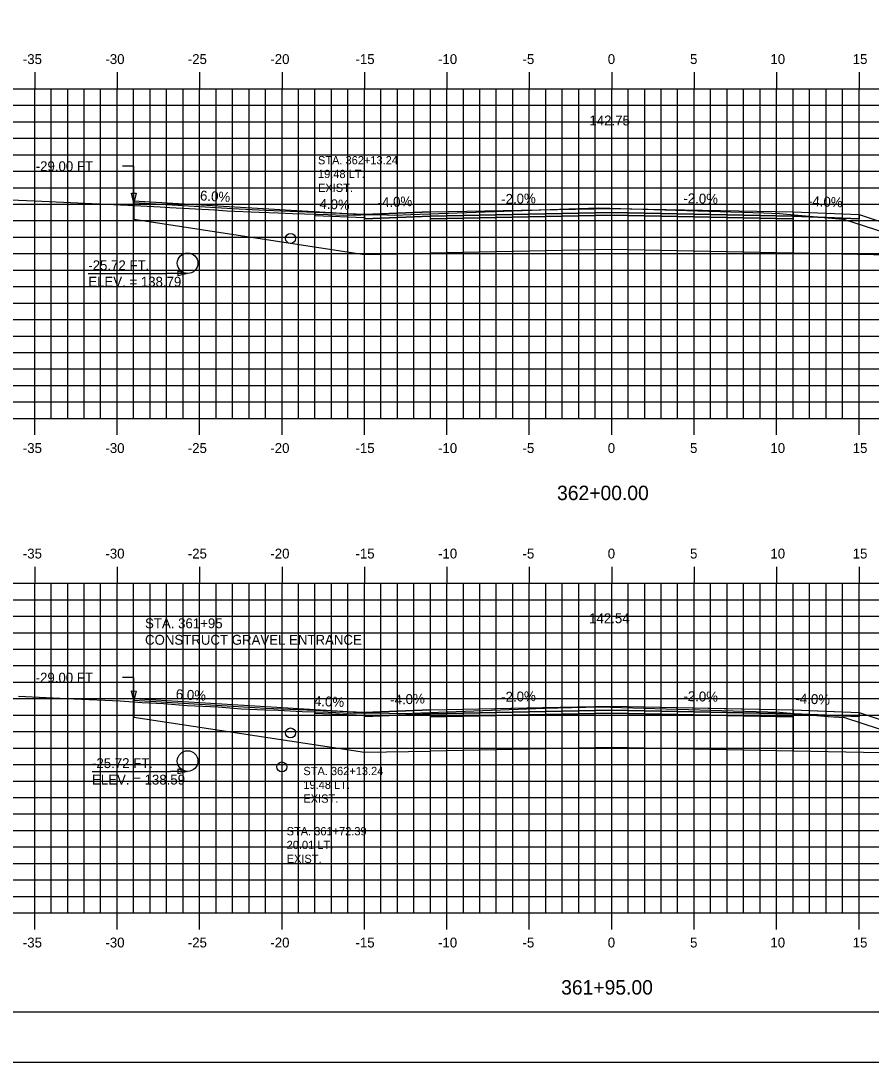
# Model space of a CAD drawing. Extents: x 1146746 to 1146916, y 608981 to 609091.
# Drawn here: x 1146793.6 to 1146845.2, y 608981.3 to 609044.5 of the extents above; entities that cross this region are included whole.
import ezdxf

# ---------------------------------------------------------------- set-up
doc = ezdxf.new("R2010")
doc.units = 0
for name, color, linetype in [('ANNOTATION', 7, 'Continuous'), ('BORDER', 7, 'Continuous'), ('D_Drainage_Culvert', 7, 'Continuous'), ('D_Roadway_Centerline', 7, 'Continuous'), ('D_Roadway_Centerline_Text', 7, 'Continuous'), ('D_Roadway_Edge_Shoulder', 7, 'Continuous'), ('D_Roadway_Edge_TW', 7, 'Continuous'), ('D_Roadway_Pavement', 7, 'Continuous'), ('D_Roadway_SubGrade', 7, 'Continuous'), ('D_Text_Monospaced', 7, 'Continuous'), ('D_Text_Standard', 7, 'Continuous'), ('H_V ANNOTATION', 7, 'Continuous'), ('MAJOR', 7, 'Continuous'), ('MINOR', 7, 'Continuous'), ('PLOT BOUNDARY', 7, 'Continuous'), ('S_Drainage_Invert', 7, 'Continuous'), ('S_Roadway_Centerline', 7, 'Continuous')]:
    doc.layers.add(name, color=color, linetype=linetype)

msp = doc.modelspace()

# ---------------------------------------------------------------- linework, layer by layer
for points in [[(1146800.428, 609033.54), (1146814.428, 609032.7), (1146818.428, 609032.86), (1146829.428, 609033.08), (1146840.428, 609032.86), (1146844.428, 609032.7), (1146852.151, 609030.126), (1146855.151, 609029.126), (1146863.344, 609033.222), (1146864.594, 609033.772), (1146865.844, 609034.173), (1146867.094, 609034.424), (1146868.344, 609034.526)], [(1146800.432, 609003.335), (1146809.117, 609002.813), (1146814.428, 609002.495), (1146815.947, 609002.556), (1146818.428, 609002.655), (1146825.253, 609002.791), (1146829.428, 609002.875), (1146836.253, 609002.738), (1146840.428, 609002.655), (1146842.909, 609002.556), (1146844.428, 609002.495), (1146849.22, 609000.898)]]:
    msp.add_lwpolyline(points)
at = {"layer": 'BORDER'}
msp.add_lwpolyline([(1146754.428, 608984.335), (1146914.428, 608984.335), (1146914.428, 609089.335), (1146754.428, 609089.335)], close=True, dxfattribs=at)
at = {"layer": 'D_Drainage_Culvert'}
for centre in [(1146803.703, 609029.751), (1146803.703, 608999.545)]:
    msp.add_circle(centre, 0.625, dxfattribs=at)
at = {"layer": 'D_Roadway_Edge_Shoulder'}
for points in [[(1146814.428, 609032.7), (1146811.428, 609032.82), (1146811.428, 609032.653), (1146814.428, 609032.533)], [(1146818.428, 609032.86), (1146814.428, 609032.7), (1146814.428, 609032.45), (1146818.428, 609032.61)], [(1146840.428, 609032.86), (1146844.428, 609032.7), (1146844.428, 609032.45), (1146840.428, 609032.61)], [(1146814.428, 609002.495), (1146811.428, 609002.615), (1146811.428, 609002.448), (1146814.428, 609002.328)], [(1146818.428, 609002.655), (1146814.428, 609002.495), (1146814.428, 609002.245), (1146818.428, 609002.405)], [(1146840.428, 609002.655), (1146844.428, 609002.495), (1146844.428, 609002.245), (1146840.428, 609002.405)]]:
    msp.add_lwpolyline(points, close=True, dxfattribs=at)
at = {"layer": 'D_Roadway_Edge_TW'}
for points in [[(1146818.428, 609032.61), (1146818.428, 609032.86), (1146829.428, 609033.08), (1146840.428, 609032.86), (1146840.428, 609032.61), (1146829.428, 609032.83)], [(1146818.428, 609002.405), (1146818.428, 609002.655), (1146829.428, 609002.875), (1146840.428, 609002.655), (1146840.428, 609002.405), (1146829.428, 609002.625)]]:
    msp.add_lwpolyline(points, close=True, dxfattribs=at)
at = {"layer": 'D_Roadway_Pavement'}
for points in [[(1146818.428, 609032.443), (1146818.428, 609032.61), (1146829.428, 609032.83), (1146840.428, 609032.61), (1146840.428, 609032.443), (1146829.428, 609032.663)], [(1146818.428, 609002.238), (1146818.428, 609002.405), (1146829.428, 609002.625), (1146840.428, 609002.405), (1146840.428, 609002.238), (1146829.428, 609002.458)]]:
    msp.add_lwpolyline(points, close=True, dxfattribs=at)
at = {"layer": 'D_Roadway_SubGrade'}
for points in [[(1146814.428, 609032.7), (1146808.428, 609032.94), (1146806.428, 609033.06), (1146800.432, 609033.42), (1146800.432, 609032.42), (1146814.428, 609030.28), (1146818.428, 609030.36), (1146818.428, 609032.61), (1146814.428, 609032.45)], [(1146818.428, 609030.36), (1146818.428, 609032.443), (1146829.428, 609032.663), (1146840.428, 609032.443), (1146840.428, 609030.36), (1146829.428, 609030.58)], [(1146840.428, 609032.443), (1146840.428, 609032.61), (1146844.428, 609032.45), (1146844.428, 609032.7), (1146844.428, 609032.7), (1146852.151, 609030.126), (1146840.428, 609030.36)], [(1146814.428, 609002.495), (1146808.428, 609002.735), (1146806.428, 609002.855), (1146800.432, 609003.215), (1146800.432, 609002.215), (1146814.428, 609000.075), (1146818.428, 609000.155), (1146818.428, 609002.405), (1146814.428, 609002.245)], [(1146840.428, 609002.238), (1146840.428, 609002.405), (1146844.428, 609002.245), (1146844.428, 609002.495), (1146844.428, 609002.495), (1146852.151, 608999.92), (1146840.428, 609000.155)], [(1146818.428, 609000.155), (1146818.428, 609002.238), (1146829.428, 609002.458), (1146840.428, 609002.238), (1146840.428, 609000.155), (1146829.428, 609000.375)]]:
    msp.add_lwpolyline(points, close=True, dxfattribs=at)
at = {"layer": 'D_Text_Standard'}
for p, q in [((1146797.677, 609029.126), (1146802.435, 609029.126)), ((1146797.904, 608998.92), (1146802.662, 608998.92))]:
    msp.add_line(p, q, dxfattribs=at)
for points in [[(1146800.432, 609033.42), (1146800.442, 609035.637), (1146799.762, 609035.637)], [(1146803.703, 609029.126), (1146803.115, 609029.126), (1146802.435, 609029.126)], [(1146800.432, 609003.215), (1146800.438, 609004.606), (1146799.758, 609004.606)], [(1146803.703, 608998.92), (1146803.342, 608998.92), (1146802.662, 608998.92)]]:
    msp.add_lwpolyline(points, dxfattribs=at)
for points in [[(1146800.432, 609033.42), (1146800.289, 609034.003), (1146800.58, 609034.001)], [(1146803.703, 609029.126), (1146803.121, 609028.98), (1146803.121, 609029.271)], [(1146800.432, 609003.215), (1146800.289, 609003.797), (1146800.58, 609003.796)], [(1146803.703, 608998.92), (1146803.121, 608998.775), (1146803.121, 608999.066)]]:
    msp.add_lwpolyline(points, close=True, dxfattribs=at)
at = {"layer": 'MAJOR'}
for p, q in [((1146794.428, 609041.337), (1146794.428, 609040.335)), ((1146799.428, 609041.337), (1146799.428, 609040.335)), ((1146804.428, 609041.337), (1146804.428, 609040.335)), ((1146809.428, 609041.337), (1146809.428, 609040.335)), ((1146814.428, 609041.337), (1146814.428, 609040.335)), ((1146819.428, 609041.337), (1146819.428, 609040.335)), ((1146824.428, 609041.337), (1146824.428, 609040.335)), ((1146829.428, 609041.337), (1146829.428, 609040.335)), ((1146834.428, 609041.337), (1146834.428, 609040.335)), ((1146839.428, 609041.337), (1146839.428, 609040.335)), ((1146844.428, 609041.337), (1146844.428, 609040.335)), ((1146759.428, 609040.335), (1146899.428, 609040.335)), ((1146759.428, 609040.335), (1146899.428, 609040.335)), ((1146794.428, 609020.335), (1146794.428, 609040.335)), ((1146799.428, 609020.335), (1146799.428, 609040.335)), ((1146804.428, 609020.335), (1146804.428, 609040.335)), ((1146809.428, 609020.335), (1146809.428, 609040.335)), ((1146814.428, 609020.335), (1146814.428, 609040.335)), ((1146819.428, 609020.335), (1146819.428, 609040.335)), ((1146824.428, 609020.335), (1146824.428, 609040.335)), ((1146829.428, 609020.335), (1146829.428, 609040.335)), ((1146834.428, 609020.335), (1146834.428, 609040.335)), ((1146839.428, 609020.335), (1146839.428, 609040.335)), ((1146844.428, 609020.335), (1146844.428, 609040.335)), ((1146759.428, 609035.335), (1146899.428, 609035.335)), ((1146759.428, 609030.335), (1146899.428, 609030.335)), ((1146759.428, 609025.335), (1146899.428, 609025.335)), ((1146759.428, 609020.335), (1146899.428, 609020.335)), ((1146759.428, 609020.335), (1146899.428, 609020.335)), ((1146794.428, 609019.333), (1146794.428, 609020.335)), ((1146799.428, 609019.333), (1146799.428, 609020.335)), ((1146804.428, 609019.333), (1146804.428, 609020.335)), ((1146809.428, 609019.333), (1146809.428, 609020.335)), ((1146814.428, 609019.333), (1146814.428, 609020.335)), ((1146819.428, 609019.333), (1146819.428, 609020.335)), ((1146824.428, 609019.333), (1146824.428, 609020.335)), ((1146829.428, 609019.333), (1146829.428, 609020.335)), ((1146834.428, 609019.333), (1146834.428, 609020.335)), ((1146839.428, 609019.333), (1146839.428, 609020.335)), ((1146844.428, 609019.333), (1146844.428, 609020.335)), ((1146794.428, 609011.337), (1146794.428, 609010.335)), ((1146799.428, 609011.337), (1146799.428, 609010.335)), ((1146804.428, 609011.337), (1146804.428, 609010.335)), ((1146809.428, 609011.337), (1146809.428, 609010.335)), ((1146814.428, 609011.337), (1146814.428, 609010.335)), ((1146819.428, 609011.337), (1146819.428, 609010.335)), ((1146824.428, 609011.337), (1146824.428, 609010.335)), ((1146829.428, 609011.337), (1146829.428, 609010.335)), ((1146834.428, 609011.337), (1146834.428, 609010.335)), ((1146839.428, 609011.337), (1146839.428, 609010.335)), ((1146844.428, 609011.337), (1146844.428, 609010.335)), ((1146759.428, 609010.335), (1146899.428, 609010.335)), ((1146759.428, 609010.335), (1146899.428, 609010.335)), ((1146794.428, 608990.335), (1146794.428, 609010.335)), ((1146799.428, 608990.335), (1146799.428, 609010.335)), ((1146804.428, 608990.335), (1146804.428, 609010.335)), ((1146809.428, 608990.335), (1146809.428, 609010.335)), ((1146814.428, 608990.335), (1146814.428, 609010.335)), ((1146819.428, 608990.335), (1146819.428, 609010.335)), ((1146824.428, 608990.335), (1146824.428, 609010.335)), ((1146829.428, 608990.335), (1146829.428, 609010.335)), ((1146834.428, 608990.335), (1146834.428, 609010.335)), ((1146839.428, 608990.335), (1146839.428, 609010.335)), ((1146844.428, 608990.335), (1146844.428, 609010.335)), ((1146759.428, 609005.335), (1146899.428, 609005.335)), ((1146759.428, 609000.335), (1146899.428, 609000.335)), ((1146759.428, 608995.335), (1146899.428, 608995.335)), ((1146759.428, 608990.335), (1146899.428, 608990.335)), ((1146759.428, 608990.335), (1146899.428, 608990.335)), ((1146794.428, 608989.333), (1146794.428, 608990.335)), ((1146799.428, 608989.333), (1146799.428, 608990.335)), ((1146804.428, 608989.333), (1146804.428, 608990.335)), ((1146809.428, 608989.333), (1146809.428, 608990.335)), ((1146814.428, 608989.333), (1146814.428, 608990.335)), ((1146819.428, 608989.333), (1146819.428, 608990.335)), ((1146824.428, 608989.333), (1146824.428, 608990.335)), ((1146829.428, 608989.333), (1146829.428, 608990.335)), ((1146834.428, 608989.333), (1146834.428, 608990.335)), ((1146839.428, 608989.333), (1146839.428, 608990.335)), ((1146844.428, 608989.333), (1146844.428, 608990.335))]:
    msp.add_line(p, q, dxfattribs=at)
at = {"layer": 'MINOR'}
for p, q in [((1146795.428, 609020.335), (1146795.428, 609040.335)), ((1146796.428, 609020.335), (1146796.428, 609040.335)), ((1146797.428, 609020.335), (1146797.428, 609040.335)), ((1146798.428, 609020.335), (1146798.428, 609040.335)), ((1146800.428, 609020.335), (1146800.428, 609040.335)), ((1146801.428, 609020.335), (1146801.428, 609040.335)), ((1146802.428, 609020.335), (1146802.428, 609040.335)), ((1146803.428, 609020.335), (1146803.428, 609040.335)), ((1146805.428, 609020.335), (1146805.428, 609040.335)), ((1146806.428, 609020.335), (1146806.428, 609040.335)), ((1146807.428, 609020.335), (1146807.428, 609040.335)), ((1146808.428, 609020.335), (1146808.428, 609040.335)), ((1146810.428, 609020.335), (1146810.428, 609040.335)), ((1146811.428, 609020.335), (1146811.428, 609040.335)), ((1146812.428, 609020.335), (1146812.428, 609040.335)), ((1146813.428, 609020.335), (1146813.428, 609040.335)), ((1146815.428, 609020.335), (1146815.428, 609040.335)), ((1146816.428, 609020.335), (1146816.428, 609040.335)), ((1146817.428, 609020.335), (1146817.428, 609040.335)), ((1146818.428, 609020.335), (1146818.428, 609040.335)), ((1146820.428, 609020.335), (1146820.428, 609040.335)), ((1146821.428, 609020.335), (1146821.428, 609040.335)), ((1146822.428, 609020.335), (1146822.428, 609040.335)), ((1146823.428, 609020.335), (1146823.428, 609040.335)), ((1146825.428, 609020.335), (1146825.428, 609040.335)), ((1146826.428, 609020.335), (1146826.428, 609040.335)), ((1146827.428, 609020.335), (1146827.428, 609040.335)), ((1146828.428, 609020.335), (1146828.428, 609040.335)), ((1146830.428, 609020.335), (1146830.428, 609040.335)), ((1146831.428, 609020.335), (1146831.428, 609040.335)), ((1146832.428, 609020.335), (1146832.428, 609040.335)), ((1146833.428, 609020.335), (1146833.428, 609040.335)), ((1146835.428, 609020.335), (1146835.428, 609040.335)), ((1146836.428, 609020.335), (1146836.428, 609040.335)), ((1146837.428, 609020.335), (1146837.428, 609040.335)), ((1146838.428, 609020.335), (1146838.428, 609040.335)), ((1146840.428, 609020.335), (1146840.428, 609040.335)), ((1146841.428, 609020.335), (1146841.428, 609040.335)), ((1146842.428, 609020.335), (1146842.428, 609040.335)), ((1146843.428, 609020.335), (1146843.428, 609040.335)), ((1146759.428, 609039.335), (1146899.428, 609039.335)), ((1146759.428, 609038.335), (1146899.428, 609038.335)), ((1146759.428, 609037.335), (1146899.428, 609037.335)), ((1146759.428, 609036.335), (1146899.428, 609036.335)), ((1146759.428, 609034.335), (1146899.428, 609034.335)), ((1146759.428, 609033.335), (1146899.428, 609033.335)), ((1146759.428, 609032.335), (1146899.428, 609032.335)), ((1146759.428, 609031.335), (1146899.428, 609031.335)), ((1146759.428, 609029.335), (1146899.428, 609029.335)), ((1146759.428, 609028.335), (1146899.428, 609028.335)), ((1146759.428, 609027.335), (1146899.428, 609027.335)), ((1146759.428, 609026.335), (1146899.428, 609026.335)), ((1146759.428, 609024.335), (1146899.428, 609024.335)), ((1146759.428, 609023.335), (1146899.428, 609023.335)), ((1146759.428, 609022.335), (1146899.428, 609022.335)), ((1146759.428, 609021.335), (1146899.428, 609021.335)), ((1146795.428, 608990.335), (1146795.428, 609010.335)), ((1146796.428, 608990.335), (1146796.428, 609010.335)), ((1146797.428, 608990.335), (1146797.428, 609010.335)), ((1146798.428, 608990.335), (1146798.428, 609010.335)), ((1146800.428, 608990.335), (1146800.428, 609010.335)), ((1146801.428, 608990.335), (1146801.428, 609010.335)), ((1146802.428, 608990.335), (1146802.428, 609010.335)), ((1146803.428, 608990.335), (1146803.428, 609010.335)), ((1146805.428, 608990.335), (1146805.428, 609010.335)), ((1146806.428, 608990.335), (1146806.428, 609010.335)), ((1146807.428, 608990.335), (1146807.428, 609010.335)), ((1146808.428, 608990.335), (1146808.428, 609010.335)), ((1146810.428, 608990.335), (1146810.428, 609010.335)), ((1146811.428, 608990.335), (1146811.428, 609010.335)), ((1146812.428, 608990.335), (1146812.428, 609010.335)), ((1146813.428, 608990.335), (1146813.428, 609010.335)), ((1146815.428, 608990.335), (1146815.428, 609010.335)), ((1146816.428, 608990.335), (1146816.428, 609010.335)), ((1146817.428, 608990.335), (1146817.428, 609010.335)), ((1146818.428, 608990.335), (1146818.428, 609010.335)), ((1146820.428, 608990.335), (1146820.428, 609010.335)), ((1146821.428, 608990.335), (1146821.428, 609010.335)), ((1146822.428, 608990.335), (1146822.428, 609010.335)), ((1146823.428, 608990.335), (1146823.428, 609010.335)), ((1146825.428, 608990.335), (1146825.428, 609010.335)), ((1146826.428, 608990.335), (1146826.428, 609010.335)), ((1146827.428, 608990.335), (1146827.428, 609010.335)), ((1146828.428, 608990.335), (1146828.428, 609010.335)), ((1146830.428, 608990.335), (1146830.428, 609010.335)), ((1146831.428, 608990.335), (1146831.428, 609010.335)), ((1146832.428, 608990.335), (1146832.428, 609010.335)), ((1146833.428, 608990.335), (1146833.428, 609010.335)), ((1146835.428, 608990.335), (1146835.428, 609010.335)), ((1146836.428, 608990.335), (1146836.428, 609010.335)), ((1146837.428, 608990.335), (1146837.428, 609010.335)), ((1146838.428, 608990.335), (1146838.428, 609010.335)), ((1146840.428, 608990.335), (1146840.428, 609010.335)), ((1146841.428, 608990.335), (1146841.428, 609010.335)), ((1146842.428, 608990.335), (1146842.428, 609010.335)), ((1146843.428, 608990.335), (1146843.428, 609010.335)), ((1146759.428, 609009.335), (1146899.428, 609009.335)), ((1146759.428, 609008.335), (1146899.428, 609008.335)), ((1146759.428, 609007.335), (1146899.428, 609007.335)), ((1146759.428, 609006.335), (1146899.428, 609006.335)), ((1146759.428, 609004.335), (1146899.428, 609004.335)), ((1146759.428, 609003.335), (1146899.428, 609003.335)), ((1146759.428, 609002.335), (1146899.428, 609002.335)), ((1146759.428, 609001.335), (1146899.428, 609001.335)), ((1146759.428, 608999.335), (1146899.428, 608999.335)), ((1146759.428, 608998.335), (1146899.428, 608998.335)), ((1146759.428, 608997.335), (1146899.428, 608997.335)), ((1146759.428, 608996.335), (1146899.428, 608996.335)), ((1146759.428, 608994.335), (1146899.428, 608994.335)), ((1146759.428, 608993.335), (1146899.428, 608993.335)), ((1146759.428, 608992.335), (1146899.428, 608992.335)), ((1146759.428, 608991.335), (1146899.428, 608991.335))]:
    msp.add_line(p, q, dxfattribs=at)
at = {"layer": 'PLOT BOUNDARY'}
msp.add_lwpolyline([(1146746.335, 608981.276), (1146916.335, 608981.276), (1146916.335, 609091.276), (1146746.335, 609091.276)], close=True, dxfattribs=at)
at = {"layer": 'S_Drainage_Invert'}
for centre in [(1146809.944, 609031.254), (1146809.944, 609001.254), (1146809.418, 608999.19)]:
    msp.add_circle(centre, 0.3, dxfattribs=at)
at = {"layer": 'S_Roadway_Centerline'}
for points in [[(1146792.515, 609033.614), (1146794.858, 609033.519), (1146795.309, 609033.499), (1146799.64, 609033.301), (1146800.079, 609033.266), (1146802.033, 609033.171), (1146802.624, 609033.125), (1146805.351, 609032.992), (1146806.077, 609032.937), (1146808.048, 609032.847), (1146809.186, 609032.804), (1146810.074, 609032.761), (1146812.22, 609032.717), (1146813.144, 609032.674), (1146815.305, 609032.703), (1146816.244, 609032.666), (1146817.245, 609032.705), (1146827.388, 609033.08), (1146828.641, 609033.111), (1146838.662, 609032.801), (1146839.609, 609032.776), (1146843.229, 609032.446), (1146843.479, 609032.432), (1146846.056, 609031.591)], [(1146793.44, 609003.479), (1146796.798, 609003.331), (1146799.621, 609003.201), (1146800.944, 609003.096), (1146802.243, 609003.033), (1146803.684, 609002.92), (1146805.556, 609002.828), (1146806.981, 609002.72), (1146808.384, 609002.656), (1146809.195, 609002.626), (1146810.642, 609002.555), (1146812.229, 609002.522), (1146813.598, 609002.46), (1146815.252, 609002.481), (1146816.539, 609002.431), (1146817.33, 609002.461), (1146825.348, 609002.759), (1146828.662, 609002.841), (1146836.794, 609002.589), (1146839.603, 609002.516), (1146842.561, 609002.246), (1146843.55, 609002.193), (1146845.656, 609001.505)]]:
    msp.add_lwpolyline(points, dxfattribs=at)

# ---------------------------------------------------------------- texts
at = {"layer": 'ANNOTATION'}
for s, rotation, p in [('6.0%', 356.56637, (1146804.443, 609033.565)), ('4.0%', 357.70944, (1146811.696, 609033.063)), ('-4.0%', 2.29061, (1146815.244, 609033.134)), ('-2.0%', 1.14576, (1146822.731, 609033.346)), ('-2.0%', 358.85424, (1146833.771, 609033.394)), ('-4.0%', 357.70939, (1146841.324, 609033.225)), ('6.0%', 356.56637, (1146802.972, 609003.314)), ('-2.0%', 1.14576, (1146822.731, 609003.141)), ('-2.0%', 358.85424, (1146833.771, 609003.188)), ('4.0%', 357.70944, (1146811.359, 609002.896)), ('-4.0%', 2.29066, (1146816.003, 609002.959)), ('-4.0%', 357.70944, (1146840.564, 609003.05))]:
    msp.add_text(s, height=0.6, rotation=rotation, dxfattribs=at).set_placement(p)
for s, p in [('STA. 361+95', (1146801.119, 609007.604)), ('CONSTRUCT GRAVEL ENTRANCE', (1146801.119, 609006.602))]:
    msp.add_text(s, height=0.6, dxfattribs=at).set_placement(p)
at = {"layer": 'D_Roadway_Centerline'}
for s, p in [('C', (1146829.423, 609033.08)), ('L', (1146829.428, 609033.073)), ('C', (1146829.423, 609002.875)), ('L', (1146829.428, 609002.868))]:
    msp.add_text(s, height=0.0146, dxfattribs=at).set_placement(p)
at = {"layer": 'D_Roadway_Centerline_Text'}
for s, p in [('142.75', (1146828.077, 609038.112)), ('142.54', (1146828.058, 609007.907))]:
    msp.add_text(s, height=0.6, dxfattribs=at).set_placement(p)
at = {"layer": 'D_Text_Monospaced'}
for s, height, p in [('STA. 362+13.24', 0.49998, (1146811.611, 609035.752)), ('19.48 LT.', 0.5, (1146811.611, 609034.918)), ('EXIST. ', 0.5, (1146811.611, 609034.078)), ('STA. 362+13.24', 0.49998, (1146810.724, 608998.692)), ('19.48 LT.', 0.5, (1146810.724, 608997.858)), ('EXIST. ', 0.5, (1146810.724, 608997.018)), ('STA. 361+72.39', 0.49998, (1146809.71, 608995.04)), ('20.01 LT.', 0.5, (1146809.71, 608994.206)), ('EXIST. ', 0.5, (1146809.71, 608993.366))]:
    msp.add_text(s, height=height, dxfattribs=at).set_placement(p)
at = {"layer": 'D_Text_Standard'}
for s, p in [('-29.00 FT', (1146794.489, 609035.337)), ('-25.72 FT.', (1146797.677, 609029.326)), ('ELEV. = 138.79', (1146797.677, 609028.326)), ('-29.00 FT', (1146794.485, 609004.306)), ('-25.72 FT.', (1146797.904, 608999.12)), ('ELEV. = 138.59', (1146797.904, 608998.12))]:
    msp.add_text(s, height=0.6, dxfattribs=at).set_placement(p)
at = {"layer": 'H_V ANNOTATION'}
for s, height, p in [('-35', 0.6, (1146793.708, 609041.835)), ('-30', 0.6, (1146798.716, 609041.835)), ('-25', 0.6, (1146803.713, 609041.835)), ('-20', 0.6, (1146808.721, 609041.835)), ('-15', 0.6, (1146813.885, 609041.835)), ('-10', 0.6, (1146818.893, 609041.835)), ('-5', 0.6, (1146824.018, 609041.835)), ('0', 0.6, (1146829.187, 609041.835)), ('5', 0.6, (1146834.179, 609041.835)), ('10', 0.6, (1146839.053, 609041.835)), ('15', 0.6, (1146844.045, 609041.835)), ('-35', 0.6, (1146793.708, 609018.235)), ('-30', 0.6, (1146798.716, 609018.235)), ('-25', 0.6, (1146803.713, 609018.235)), ('-20', 0.6, (1146808.721, 609018.235)), ('-15', 0.6, (1146813.885, 609018.235)), ('-10', 0.6, (1146818.893, 609018.235)), ('-5', 0.6, (1146824.018, 609018.235)), ('0', 0.6, (1146829.187, 609018.235)), ('5', 0.6, (1146834.179, 609018.235)), ('10', 0.6, (1146839.053, 609018.235)), ('15', 0.6, (1146844.045, 609018.235)), ('362+00.00', 0.875, (1146826.112, 609015.378)), ('-35', 0.6, (1146793.708, 609011.835)), ('-30', 0.6, (1146798.716, 609011.835)), ('-25', 0.6, (1146803.713, 609011.835)), ('-20', 0.6, (1146808.721, 609011.835)), ('-15', 0.6, (1146813.885, 609011.835)), ('-10', 0.6, (1146818.893, 609011.835)), ('-5', 0.6, (1146824.018, 609011.835)), ('0', 0.6, (1146829.187, 609011.835)), ('5', 0.6, (1146834.179, 609011.835)), ('10', 0.6, (1146839.053, 609011.835)), ('15', 0.6, (1146844.045, 609011.835)), ('-35', 0.6, (1146793.708, 608988.235)), ('-30', 0.6, (1146798.716, 608988.235)), ('-25', 0.6, (1146803.713, 608988.235)), ('-20', 0.6, (1146808.721, 608988.235)), ('-15', 0.6, (1146813.885, 608988.235)), ('-10', 0.6, (1146818.893, 608988.235)), ('-5', 0.6, (1146824.018, 608988.235)), ('0', 0.6, (1146829.187, 608988.235)), ('5', 0.6, (1146834.179, 608988.235)), ('10', 0.6, (1146839.053, 608988.235)), ('15', 0.6, (1146844.045, 608988.235)), ('361+95.00', 0.875, (1146826.361, 608985.378))]:
    msp.add_text(s, height=height, dxfattribs=at).set_placement(p)
at = {"layer": 'S_Roadway_Centerline'}
for s, p in [('L', (1146828.633, 609033.104)), ('C', (1146828.636, 609033.111)), ('L', (1146828.654, 609002.833)), ('C', (1146828.657, 609002.841))]:
    msp.add_text(s, height=0.0146, dxfattribs=at).set_placement(p)

doc.saveas('drawing.dxf')
